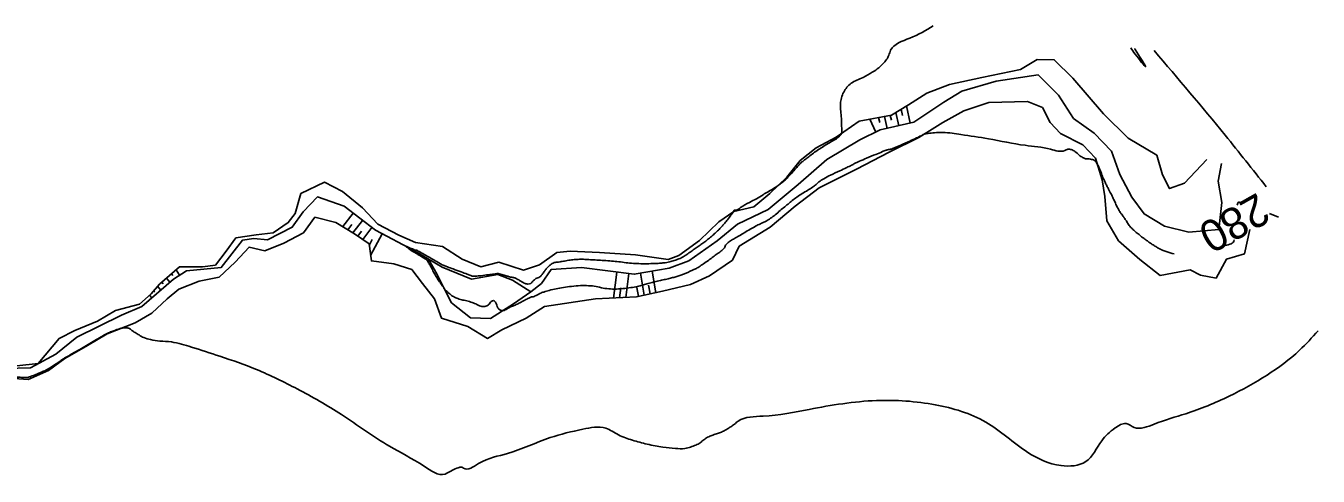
# Model space of a CAD drawing. Extents: x -475575 to -473225, y -1116053 to -1114104.
# Drawn here: x -473731.5 to -473568.7, y -1114786.5 to -1114729.7 of the extents above; entities that cross this region are included whole.
import ezdxf

# ---------------------------------------------------------------- set-up
doc = ezdxf.new("R2010")
doc.units = 0
for name, color, linetype in [('Vrstevnice_hlavni', 7, 'Continuous'), ('Vrstevnice_popis', 7, 'Continuous'), ('Vrstevnice_vedlejsi', 7, 'Continuous'), ('Vrstva_10', 7, 'Continuous')]:
    doc.layers.add(name, color=color, linetype=linetype)

msp = doc.modelspace()

# ---------------------------------------------------------------- linework, layer by layer
at = {"layer": 'Vrstevnice_hlavni'}
msp.add_line((-473574.83, -1114753.39), (-473573.68, -1114753.83), dxfattribs=at)
for points in [[(-473617.2, -1114729.7), (-473620.15, -1114731.26), (-473622.56, -1114732.78), (-473622.79, -1114733.41), (-473623.11, -1114733.99), (-473623.53, -1114734.51), (-473624.04, -1114734.98), (-473624.87, -1114735.54), (-473626.04, -1114736.2), (-473627.53, -1114736.95), (-473628.48, -1114738.07), (-473628.89, -1114739.54), (-473628.76, -1114741.38), (-473628.73, -1114742.66), (-473628.81, -1114743.4), (-473628.99, -1114743.6), (-473629.15, -1114743.75), (-473629.29, -1114743.86), (-473629.4, -1114743.94), (-473629.73, -1114744.13), (-473630.26, -1114744.45), (-473630.99, -1114744.88), (-473631.67, -1114745.32), (-473632.3, -1114745.76), (-473632.88, -1114746.21), (-473633.33, -1114746.55), (-473633.64, -1114746.8), (-473633.82, -1114746.94), (-473634.1, -1114747.23), (-473634.5, -1114747.68), (-473635, -1114748.28), (-473635.5, -1114748.81), (-473635.98, -1114749.27), (-473636.46, -1114749.65), (-473637.34, -1114750.23), (-473638.64, -1114751.01), (-473640.34, -1114751.98), (-473641.47, -1114752.62), (-473642.05, -1114752.94), (-473642.06, -1114752.94), (-473642.09, -1114752.94), (-473642.15, -1114752.95), (-473642.23, -1114752.96), (-473642.29, -1114752.99), (-473642.33, -1114753.03), (-473642.34, -1114753.09), (-473642.46, -1114753.28), (-473642.69, -1114753.6), (-473643.04, -1114754.06), (-473643.37, -1114754.48), (-473643.69, -1114754.85), (-473643.99, -1114755.19), (-473644.36, -1114755.56), (-473644.78, -1114755.95), (-473645.27, -1114756.38), (-473645.75, -1114756.77), (-473646.23, -1114757.12), (-473646.7, -1114757.45), (-473647.19, -1114757.79), (-473647.71, -1114758.16), (-473648.24, -1114758.54), (-473648.7, -1114758.83), (-473649.09, -1114759.04), (-473649.39, -1114759.15), (-473649.69, -1114759.25), (-473649.98, -1114759.35), (-473650.26, -1114759.43), (-473650.59, -1114759.51), (-473650.96, -1114759.58)], [(-473591.82, -1114732.54), (-473591.73, -1114732.69), (-473590.44, -1114734.87), (-473591.74, -1114733.26), (-473592.29, -1114732.49)], [(-473575.23, -1114750), (-473580.41, -1114743.5), (-473589.36, -1114732.82)], [(-473622.72, -1114745.29), (-473622.57, -1114745.27), (-473622.09, -1114745.08), (-473621.29, -1114744.74), (-473620.16, -1114744.24), (-473619.3, -1114743.84), (-473618.72, -1114743.56), (-473618.41, -1114743.39), (-473617.85, -1114743.27), (-473617.03, -1114743.19), (-473615.96, -1114743.16), (-473613.7, -1114743.41), (-473610.25, -1114743.95), (-473605.62, -1114744.77), (-473602.4, -1114745.26), (-473600.61, -1114745.43), (-473600.23, -1114745.27), (-473599.81, -1114745.31), (-473599.34, -1114745.55), (-473598.82, -1114746), (-473598.37, -1114746.31), (-473597.99, -1114746.46), (-473597.67, -1114746.48), (-473597.38, -1114746.51), (-473597.11, -1114746.58), (-473596.87, -1114746.68), (-473596.6, -1114747), (-473596.32, -1114747.54), (-473596.01, -1114748.31), (-473595.73, -1114748.98), (-473595.48, -1114749.54), (-473595.26, -1114750), (-473595.06, -1114750.39), (-473594.89, -1114750.72), (-473594.74, -1114750.99), (-473594.57, -1114751.35), (-473594.35, -1114751.8), (-473594.11, -1114752.36), (-473593.86, -1114752.83), (-473593.62, -1114753.23), (-473593.38, -1114753.56), (-473593.13, -1114753.92), (-473592.86, -1114754.32), (-473592.58, -1114754.76), (-473592.24, -1114755.18), (-473591.83, -1114755.57), (-473591.37, -1114755.95), (-473590.93, -1114756.3), (-473590.51, -1114756.62), (-473590.11, -1114756.91), (-473589.7, -1114757.2), (-473589.26, -1114757.48), (-473588.8, -1114757.76), (-473588.32, -1114758), (-473587.84, -1114758.18), (-473586.85, -1114758.47)], [(-473676.78, -1114764.22), (-473676.12, -1114764.36), (-473675.47, -1114764.54), (-473674.84, -1114764.78), (-473674.22, -1114765.07), (-473673.69, -1114765.11), (-473673.25, -1114764.91), (-473672.9, -1114764.46), (-473672.59, -1114764.37), (-473672.31, -1114764.64), (-473672.06, -1114765.26), (-473671.72, -1114765.58), (-473671.28, -1114765.6), (-473670.74, -1114765.31), (-473670.35, -1114765.11), (-473670.1, -1114765.01), (-473670.01, -1114764.99), (-473669.73, -1114764.87), (-473669.28, -1114764.63), (-473668.66, -1114764.29), (-473668.17, -1114764.05), (-473667.82, -1114763.9), (-473667.61, -1114763.87), (-473667.36, -1114763.78), (-473667.07, -1114763.65), (-473666.75, -1114763.46), (-473666.25, -1114763.28), (-473665.57, -1114763.08), (-473664.72, -1114762.88), (-473663.78, -1114762.71), (-473662.76, -1114762.57), (-473661.65, -1114762.47), (-473660.62, -1114762.48), (-473659.67, -1114762.58), (-473658.79, -1114762.78), (-473657.85, -1114762.89), (-473656.84, -1114762.89), (-473655.77, -1114762.79), (-473654.87, -1114762.66), (-473654.14, -1114762.51), (-473653.58, -1114762.33), (-473652.96, -1114762.16), (-473652.3, -1114761.99), (-473651.58, -1114761.83), (-473650.92, -1114761.68), (-473650.31, -1114761.53), (-473649.76, -1114761.39), (-473649.25, -1114761.23), (-473648.77, -1114761.07), (-473648.33, -1114760.89), (-473647.92, -1114760.71), (-473647.53, -1114760.54), (-473647.16, -1114760.37), (-473646.7, -1114760.1), (-473646.14, -1114759.72), (-473645.48, -1114759.25), (-473644.91, -1114758.83), (-473644.41, -1114758.47), (-473643.99, -1114758.17), (-473643.68, -1114757.89), (-473643.46, -1114757.62), (-473643.35, -1114757.37), (-473643.11, -1114757.1), (-473642.74, -1114756.82), (-473642.24, -1114756.53), (-473641.66, -1114756.19), (-473641, -1114755.8), (-473640.26, -1114755.36), (-473639.59, -1114754.99), (-473638.97, -1114754.67), (-473638.41, -1114754.42), (-473637.84, -1114754.08), (-473637.25, -1114753.65), (-473636.64, -1114753.14), (-473636.05, -1114752.64), (-473635.49, -1114752.18), (-473634.96, -1114751.73), (-473634.37, -1114751.3), (-473633.71, -1114750.87), (-473633, -1114750.45), (-473632.41, -1114750.07), (-473631.94, -1114749.71), (-473631.6, -1114749.39), (-473631, -1114748.99), (-473630.12, -1114748.53), (-473628.98, -1114748), (-473628.1, -1114747.58), (-473627.48, -1114747.27), (-473627.11, -1114747.08), (-473626.49, -1114746.78), (-473625.59, -1114746.4), (-473624.42, -1114745.91), (-473623.6, -1114745.57), (-473623.13, -1114745.38), (-473623, -1114745.35), (-473622.86, -1114745.31), (-473622.72, -1114745.29)], [(-473578.38, -1114752.06), (-473578.66, -1114751.96), (-473578.76, -1114751.97), (-473578.83, -1114752.05), (-473578.88, -1114752.34)], [(-473650.96, -1114759.58), (-473651.38, -1114759.63), (-473651.99, -1114759.68), (-473652.79, -1114759.7), (-473653.79, -1114759.71), (-473654.75, -1114759.68), (-473655.68, -1114759.61), (-473656.59, -1114759.49), (-473657.5, -1114759.4), (-473658.43, -1114759.32), (-473659.37, -1114759.26), (-473660.21, -1114759.21), (-473660.95, -1114759.17), (-473661.6, -1114759.15), (-473662.26, -1114759.18), (-473662.95, -1114759.25), (-473663.66, -1114759.38), (-473664.21, -1114759.47), (-473664.6, -1114759.53), (-473664.82, -1114759.54), (-473665.07, -1114759.63), (-473665.33, -1114759.78), (-473665.62, -1114760.01), (-473665.89, -1114760.28), (-473666.15, -1114760.61), (-473666.41, -1114760.98), (-473666.65, -1114761.26), (-473666.89, -1114761.44), (-473667.13, -1114761.52), (-473667.37, -1114761.67), (-473667.63, -1114761.9), (-473667.9, -1114762.19), (-473668.27, -1114762.27), (-473668.74, -1114762.15), (-473669.31, -1114761.82), (-473669.75, -1114761.59), (-473670.08, -1114761.45), (-473670.29, -1114761.42), (-473670.6, -1114761.35), (-473671.01, -1114761.23), (-473671.54, -1114761.08), (-473671.91, -1114760.98), (-473672.13, -1114760.94), (-473672.2, -1114760.96), (-473672.57, -1114761.02), (-473673.23, -1114761.1), (-473674.18, -1114761.22), (-473674.87, -1114761.28), (-473675.3, -1114761.27), (-473675.47, -1114761.2), (-473675.92, -1114761.02), (-473676.66, -1114760.75), (-473677.69, -1114760.37), (-473678.42, -1114760.1), (-473678.84, -1114759.94), (-473678.96, -1114759.89), (-473679.39, -1114759.65), (-473680.12, -1114759.24), (-473681.16, -1114758.64), (-473681.89, -1114758.23), (-473682.31, -1114758.02), (-473682.42, -1114758), (-473682.51, -1114757.98), (-473682.59, -1114757.96), (-473682.66, -1114757.93), (-473682.83, -1114757.85), (-473683.09, -1114757.74), (-473683.46, -1114757.57), (-473683.58, -1114757.55), (-473683.46, -1114757.68), (-473683.1, -1114757.94), (-473682.84, -1114758.13), (-473682.68, -1114758.23), (-473682.62, -1114758.25), (-473682.41, -1114758.37), (-473682.04, -1114758.59), (-473681.52, -1114758.91), (-473681.15, -1114759.14), (-473680.95, -1114759.28), (-473680.92, -1114759.34), (-473680.78, -1114759.58), (-473680.55, -1114760), (-473680.23, -1114760.61), (-473679.9, -1114761.19), (-473679.57, -1114761.73), (-473679.22, -1114762.25), (-473678.99, -1114762.6), (-473678.88, -1114762.77), (-473678.88, -1114762.78), (-473678.86, -1114762.79), (-473678.85, -1114762.83), (-473678.82, -1114762.88), (-473678.65, -1114763.04), (-473678.34, -1114763.32), (-473677.89, -1114763.7), (-473677.37, -1114764), (-473676.78, -1114764.22)], [(-473579.28, -1114756.7), (-473579.35, -1114756.97), (-473579.52, -1114757.11), (-473579.81, -1114757.24), (-473580.67, -1114757.48)]]:
    msp.add_spline(points, degree=3, dxfattribs=at)
at = {"layer": 'Vrstevnice_vedlejsi'}
for points in [[(-473568.69, -1114768.16), (-473571.04, -1114770.63), (-473575.13, -1114773.75), (-473579.9, -1114776.42), (-473585.36, -1114778.63), (-473589.35, -1114779.94), (-473591.86, -1114780.36), (-473592.9, -1114779.88), (-473594.27, -1114780.43), (-473595.96, -1114782.04), (-473597.98, -1114784.68), (-473601.09, -1114785.17), (-473605.29, -1114783.51), (-473610.58, -1114779.69), (-473616.93, -1114777.51), (-473624.34, -1114776.97), (-473632.81, -1114778.08), (-473638.61, -1114778.94), (-473641.76, -1114779.57), (-473642.25, -1114779.95), (-473642.7, -1114780.28), (-473643.13, -1114780.55), (-473643.53, -1114780.78), (-473643.99, -1114780.99), (-473644.51, -1114781.18), (-473645.09, -1114781.37), (-473645.62, -1114781.61), (-473646.11, -1114781.92), (-473646.56, -1114782.29), (-473647.11, -1114782.59), (-473647.76, -1114782.84), (-473648.51, -1114783.02), (-473649.68, -1114783.02), (-473651.25, -1114782.84), (-473653.24, -1114782.48), (-473655.1, -1114781.97), (-473656.84, -1114781.3), (-473658.46, -1114780.47), (-473661.34, -1114780.59), (-473665.46, -1114781.65), (-473670.83, -1114783.65), (-473674.48, -1114784.93), (-473676.4, -1114785.51), (-473676.61, -1114785.38), (-473677.06, -1114785.45), (-473677.76, -1114785.74), (-473678.71, -1114786.25), (-473681.36, -1114785.25), (-473685.71, -1114782.74), (-473691.75, -1114778.74), (-473697.33, -1114775.51), (-473702.45, -1114773.06), (-473707.09, -1114771.38), (-473710.67, -1114770.22), (-473713.19, -1114769.58), (-473714.64, -1114769.46), (-473715.81, -1114769.28), (-473716.68, -1114769.03), (-473717.25, -1114768.7), (-473717.76, -1114768.4), (-473718.18, -1114768.12), (-473718.54, -1114767.86), (-473719.03, -1114767.79), (-473719.66, -1114767.89), (-473720.44, -1114768.17), (-473720.98, -1114768.37), (-473721.29, -1114768.5), (-473721.38, -1114768.54), (-473721.7, -1114768.72), (-473722.25, -1114769.05), (-473723.04, -1114769.52), (-473723.87, -1114770.02), (-473724.74, -1114770.52), (-473725.67, -1114771.05), (-473726.29, -1114771.41), (-473726.62, -1114771.6), (-473726.66, -1114771.62), (-473726.89, -1114771.77), (-473727.32, -1114772.07), (-473727.95, -1114772.49), (-473728.41, -1114772.8), (-473728.7, -1114772.99), (-473728.83, -1114773.06), (-473729.16, -1114773.21), (-473729.7, -1114773.44)], [(-473729.7, -1114773.44), (-473730.44, -1114773.75), (-473731, -1114773.96), (-473731.36, -1114774.07), (-473731.54, -1114774.07), (-473731.93, -1114774.05), (-473732.53, -1114774.02), (-473733.35, -1114773.96), (-473733.92, -1114773.94), (-473734.24, -1114773.94), (-473734.31, -1114773.96), (-473734.53, -1114774.21), (-473734.89, -1114774.66), (-473735.39, -1114775.34), (-473735.75, -1114775.81), (-473735.95, -1114776.09), (-473736, -1114776.16), (-473736.31, -1114776.33), (-473736.87, -1114776.6), (-473737.69, -1114776.96), (-473738.44, -1114777.22), (-473739.13, -1114777.36), (-473739.75, -1114777.4), (-473740.22, -1114777.44), (-473740.53, -1114777.48), (-473740.69, -1114777.52), (-473741.15, -1114777.59), (-473741.9, -1114777.69), (-473742.95, -1114777.83), (-473743.7, -1114777.92), (-473744.15, -1114777.97), (-473744.3, -1114777.97), (-473744.68, -1114777.9), (-473745.29, -1114777.75), (-473746.12, -1114777.51), (-473746.7, -1114777.35), (-473747.02, -1114777.26), (-473747.08, -1114777.24), (-473747.14, -1114777.23), (-473747.2, -1114777.21), (-473747.25, -1114777.19), (-473747.65, -1114777.11), (-473748.39, -1114776.97), (-473749.47, -1114776.77), (-473750.19, -1114776.64), (-473750.56, -1114776.57), (-473750.58, -1114776.57), (-473750.86, -1114776.62), (-473751.42, -1114776.71), (-473752.25, -1114776.84), (-473752.83, -1114776.92), (-473753.17, -1114776.95), (-473753.27, -1114776.92), (-473753.44, -1114776.94), (-473753.68, -1114777.01), (-473753.99, -1114777.13), (-473754.49, -1114777.33), (-473755.17, -1114777.63), (-473756.05, -1114778.02), (-473756.78, -1114778.34), (-473757.37, -1114778.59), (-473757.82, -1114778.76), (-473758.2, -1114778.91), (-473758.5, -1114779.02), (-473758.73, -1114779.1), (-473758.99, -1114779.16), (-473759.27, -1114779.2), (-473759.57, -1114779.21), (-473759.96, -1114779.22), (-473760.44, -1114779.23), (-473760.99, -1114779.25), (-473761.5, -1114779.25), (-473761.94, -1114779.24), (-473762.33, -1114779.23), (-473762.78, -1114779.19), (-473763.28, -1114779.14), (-473763.84, -1114779.06), (-473764.26, -1114779), (-473764.55, -1114778.98), (-473764.7, -1114778.98), (-473764.89, -1114779.03), (-473765.11, -1114779.14), (-473765.38, -1114779.31), (-473765.67, -1114779.51), (-473765.98, -1114779.74), (-473766.31, -1114779.99), (-473766.65, -1114780.21), (-473767, -1114780.39), (-473767.36, -1114780.52), (-473767.72, -1114780.64), (-473768.08, -1114780.75), (-473768.44, -1114780.86), (-473768.8, -1114780.86), (-473769.18, -1114780.77), (-473769.56, -1114780.58), (-473769.88, -1114780.42), (-473770.14, -1114780.31)]]:
    msp.add_spline(points, degree=3, dxfattribs=at)
at = {"layer": 'Vrstva_10'}
for p, q in [((-473620.57, -1114739.8), (-473620.08, -1114741.97)), ((-473624.08, -1114741.28), (-473623.94, -1114741.89)), ((-473623.34, -1114741.15), (-473623, -1114742.64)), ((-473622.6, -1114741.01), (-473622.47, -1114741.59)), ((-473621.92, -1114740.65), (-473621.54, -1114742.3)), ((-473621.24, -1114740.23), (-473621.07, -1114740.99)), ((-473625.19, -1114741.49), (-473624.42, -1114743.1)), ((-473691.61, -1114755.03), (-473690.3, -1114753.32)), ((-473690.32, -1114755.82), (-473689.11, -1114754.24)), ((-473690.97, -1114755.42), (-473690.46, -1114754.77)), ((-473689.7, -1114756.24), (-473689.22, -1114755.62)), ((-473689.08, -1114756.66), (-473687.92, -1114755.15)), ((-473688.09, -1114758.67), (-473686.64, -1114755.92)), ((-473688.26, -1114757.39), (-473687.88, -1114756.67)), ((-473713.18, -1114760.97), (-473713.03, -1114761.21)), ((-473712.61, -1114760.47), (-473712.17, -1114761.16)), ((-473657.47, -1114764.04), (-473657.06, -1114760.76)), ((-473655.95, -1114763.96), (-473655.57, -1114760.95)), ((-473653.61, -1114763.68), (-473654.09, -1114760.91)), ((-473652.15, -1114763.37), (-473652.61, -1114760.65)), ((-473714.93, -1114762.55), (-473714.51, -1114763.03)), ((-473714.39, -1114762.02), (-473714.21, -1114762.23)), ((-473713.82, -1114761.53), (-473713.38, -1114762.04)), ((-473652.88, -1114763.52), (-473653.07, -1114762.43)), ((-473715.95, -1114763.66), (-473715.64, -1114764.01)), ((-473715.43, -1114763.11), (-473715.29, -1114763.27)), ((-473656.71, -1114764), (-473656.55, -1114762.74)), ((-473654.35, -1114763.83), (-473654.54, -1114762.71))]:
    msp.add_line(p, q, dxfattribs=at)
for points in [[(-473582.72, -1114746.56), (-473585.53, -1114749.53), (-473587.42, -1114750.24), (-473588.32, -1114748.48), (-473589.03, -1114746.02), (-473592.61, -1114743.86), (-473595.75, -1114740.78), (-473599.59, -1114736.3), (-473601.95, -1114733.98), (-473604.1, -1114733.96), (-473606.21, -1114735.22), (-473611.06, -1114736.22), (-473615.14, -1114737.08), (-473618.02, -1114738.18), (-473620.33, -1114739.65), (-473622.45, -1114740.98), (-473626.53, -1114741.73), (-473629.41, -1114743.76), (-473631.95, -1114745.07), (-473633.96, -1114746.67), (-473635.65, -1114748.79), (-473637.8, -1114750.87), (-473639.8, -1114752.53), (-473642.33, -1114753.13), (-473644.2, -1114754.42)], [(-473644.4, -1114756.83), (-473641.85, -1114754.7), (-473637.99, -1114752.88), (-473634.2, -1114749.73), (-473630.61, -1114746.56), (-473626.46, -1114744.08), (-473623.86, -1114742.83), (-473619.62, -1114741.86), (-473615.86, -1114739.34), (-473613.57, -1114737.93), (-473609.26, -1114736.7), (-473603.99, -1114735.86), (-473601.39, -1114738.45), (-473599.51, -1114741.38), (-473596.93, -1114743.22), (-473594.72, -1114745.5), (-473593.69, -1114748.47), (-473592.18, -1114751.31), (-473590.62, -1114753.42), (-473588.07, -1114754.98), (-473584.97, -1114755.73), (-473581.21, -1114755.4), (-473580.84, -1114751.98), (-473581.27, -1114749.31), (-473580.88, -1114747.05)], [(-473641.66, -1114757.51), (-473637.75, -1114755.1), (-473634.6, -1114752.43), (-473631.55, -1114750.15), (-473626.85, -1114747.79), (-473622.74, -1114745.64), (-473619.01, -1114743.79), (-473615.98, -1114741.89), (-473613.35, -1114740.43), (-473610.19, -1114739.39), (-473605.31, -1114739.23), (-473603.44, -1114740.02), (-473602.44, -1114741.91), (-473601.14, -1114743.28), (-473598.33, -1114744.72), (-473596.73, -1114746.41), (-473595.9, -1114749.14), (-473595.56, -1114751.23), (-473595.31, -1114754.28), (-473593.83, -1114756.81), (-473591.17, -1114759.16), (-473588.6, -1114761.18), (-473584.8, -1114760.49), (-473583.51, -1114761.15), (-473581.55, -1114761.52), (-473580.26, -1114759.14), (-473577.97, -1114758.45), (-473577.31, -1114755.38)], [(-473644.2, -1114754.42), (-473646.66, -1114756.78), (-473649.27, -1114758.68), (-473650.59, -1114759.16), (-473654.71, -1114758.58), (-473659.24, -1114758.28), (-473662.93, -1114758.11), (-473664.62, -1114758.28), (-473666.81, -1114759.87), (-473668.81, -1114760.51), (-473671.92, -1114759.51), (-473674.22, -1114760.12), (-473676.57, -1114759.14), (-473679.04, -1114757.54), (-473682.44, -1114757.03), (-473684.55, -1114756.1), (-473687.18, -1114754.74), (-473689.13, -1114752.65), (-473691.64, -1114750.61), (-473693.91, -1114749.44), (-473696.87, -1114750.86), (-473697.59, -1114753.36), (-473698.47, -1114754.51), (-473700.37, -1114755.8), (-473702.51, -1114756.08), (-473705.06, -1114756.46), (-473706.3, -1114758.14), (-473707.64, -1114759.91), (-473709.29, -1114760.12), (-473712.18, -1114760.09), (-473714.71, -1114762.3), (-473715.76, -1114763.49), (-473717.21, -1114764.81), (-473720.22, -1114765.61), (-473722.5, -1114766.97), (-473725.38, -1114768.12), (-473727.35, -1114769.13), (-473729.96, -1114772.29), (-473732.65, -1114772.61)], [(-473734.09, -1114772.92), (-473730.95, -1114772.85), (-473727.77, -1114771.11), (-473725.1, -1114768.97), (-473719.49, -1114766.19), (-473716.9, -1114765.11), (-473712.94, -1114761.66), (-473711.31, -1114760.61), (-473706.91, -1114760.17), (-473704.24, -1114756.75), (-473702.79, -1114756.53), (-473701.1, -1114756.68), (-473697.96, -1114755.1), (-473696.57, -1114753.18), (-473694.78, -1114751.28), (-473691.44, -1114752.45), (-473687.49, -1114755.47), (-473682.54, -1114758.09), (-473679.09, -1114760.14), (-473675.38, -1114761.66), (-473672.07, -1114761.07), (-473670.19, -1114761.78), (-473667.92, -1114763.27), (-473666.57, -1114762.21), (-473665.34, -1114760.45), (-473661.5, -1114760.2), (-473654.86, -1114761.04), (-473650.45, -1114760.29), (-473647.97, -1114759.34), (-473644.4, -1114756.83)], [(-473734.18, -1114774.09), (-473731.23, -1114774.3), (-473728.69, -1114773.16), (-473726.64, -1114771.67), (-473723.78, -1114770.03), (-473721.29, -1114768.56), (-473717.75, -1114767.15), (-473715.67, -1114765.94), (-473713.71, -1114764.13), (-473712.26, -1114762.91), (-473709.7, -1114761.91), (-473707.18, -1114761.42), (-473705.16, -1114759.52), (-473703.4, -1114757.62), (-473701.41, -1114758.1), (-473699.01, -1114757.13), (-473696.56, -1114755.82), (-473695.11, -1114753.84), (-473692.48, -1114754.5), (-473690.12, -1114755.94), (-473688.29, -1114757.21), (-473687.99, -1114759.36), (-473685.16, -1114759.73), (-473682.91, -1114760.42), (-473681.53, -1114762.21), (-473680.03, -1114764.13), (-473679.14, -1114766.59), (-473675.85, -1114767.62), (-473673.34, -1114769.14), (-473671.54, -1114768.05), (-473668.47, -1114766.56), (-473666.19, -1114765.11), (-473659.76, -1114764.16), (-473654.58, -1114763.88), (-473651.31, -1114763.19), (-473647.8, -1114762.33), (-473645.38, -1114761.25), (-473642.5, -1114759.25), (-473641.66, -1114757.51)], [(-473667.92, -1114763.27), (-473670.09, -1114764.77), (-473672.99, -1114766.64), (-473675.51, -1114766.52), (-473677.91, -1114764.64), (-473678.87, -1114762.77), (-473679.69, -1114761.08), (-473680.81, -1114759.12)]]:
    msp.add_lwpolyline(points, dxfattribs=at)

# ---------------------------------------------------------------- texts
at = {"layer": 'Vrstevnice_popis'}
msp.add_text(' 280 ', height=4, rotation=209.3995, dxfattribs=at).set_placement((-473575.03, -1114749.94))

doc.saveas('drawing.dxf')
